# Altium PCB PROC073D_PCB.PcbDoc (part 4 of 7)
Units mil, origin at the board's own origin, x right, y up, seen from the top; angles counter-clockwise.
Board outline 2165.35 x 2695.12 mil, 8 copper layers (Top Layer, L2_GND, L3_SIGNAL 1, L4_SIGNAL 2, L5_SIGNAL 3, L6_SIGNAL 4, L7_GND, Bottom Layer), stack 56.1 mil thick; 414 components, 319 nets, 1353 pads, 1669 vias.
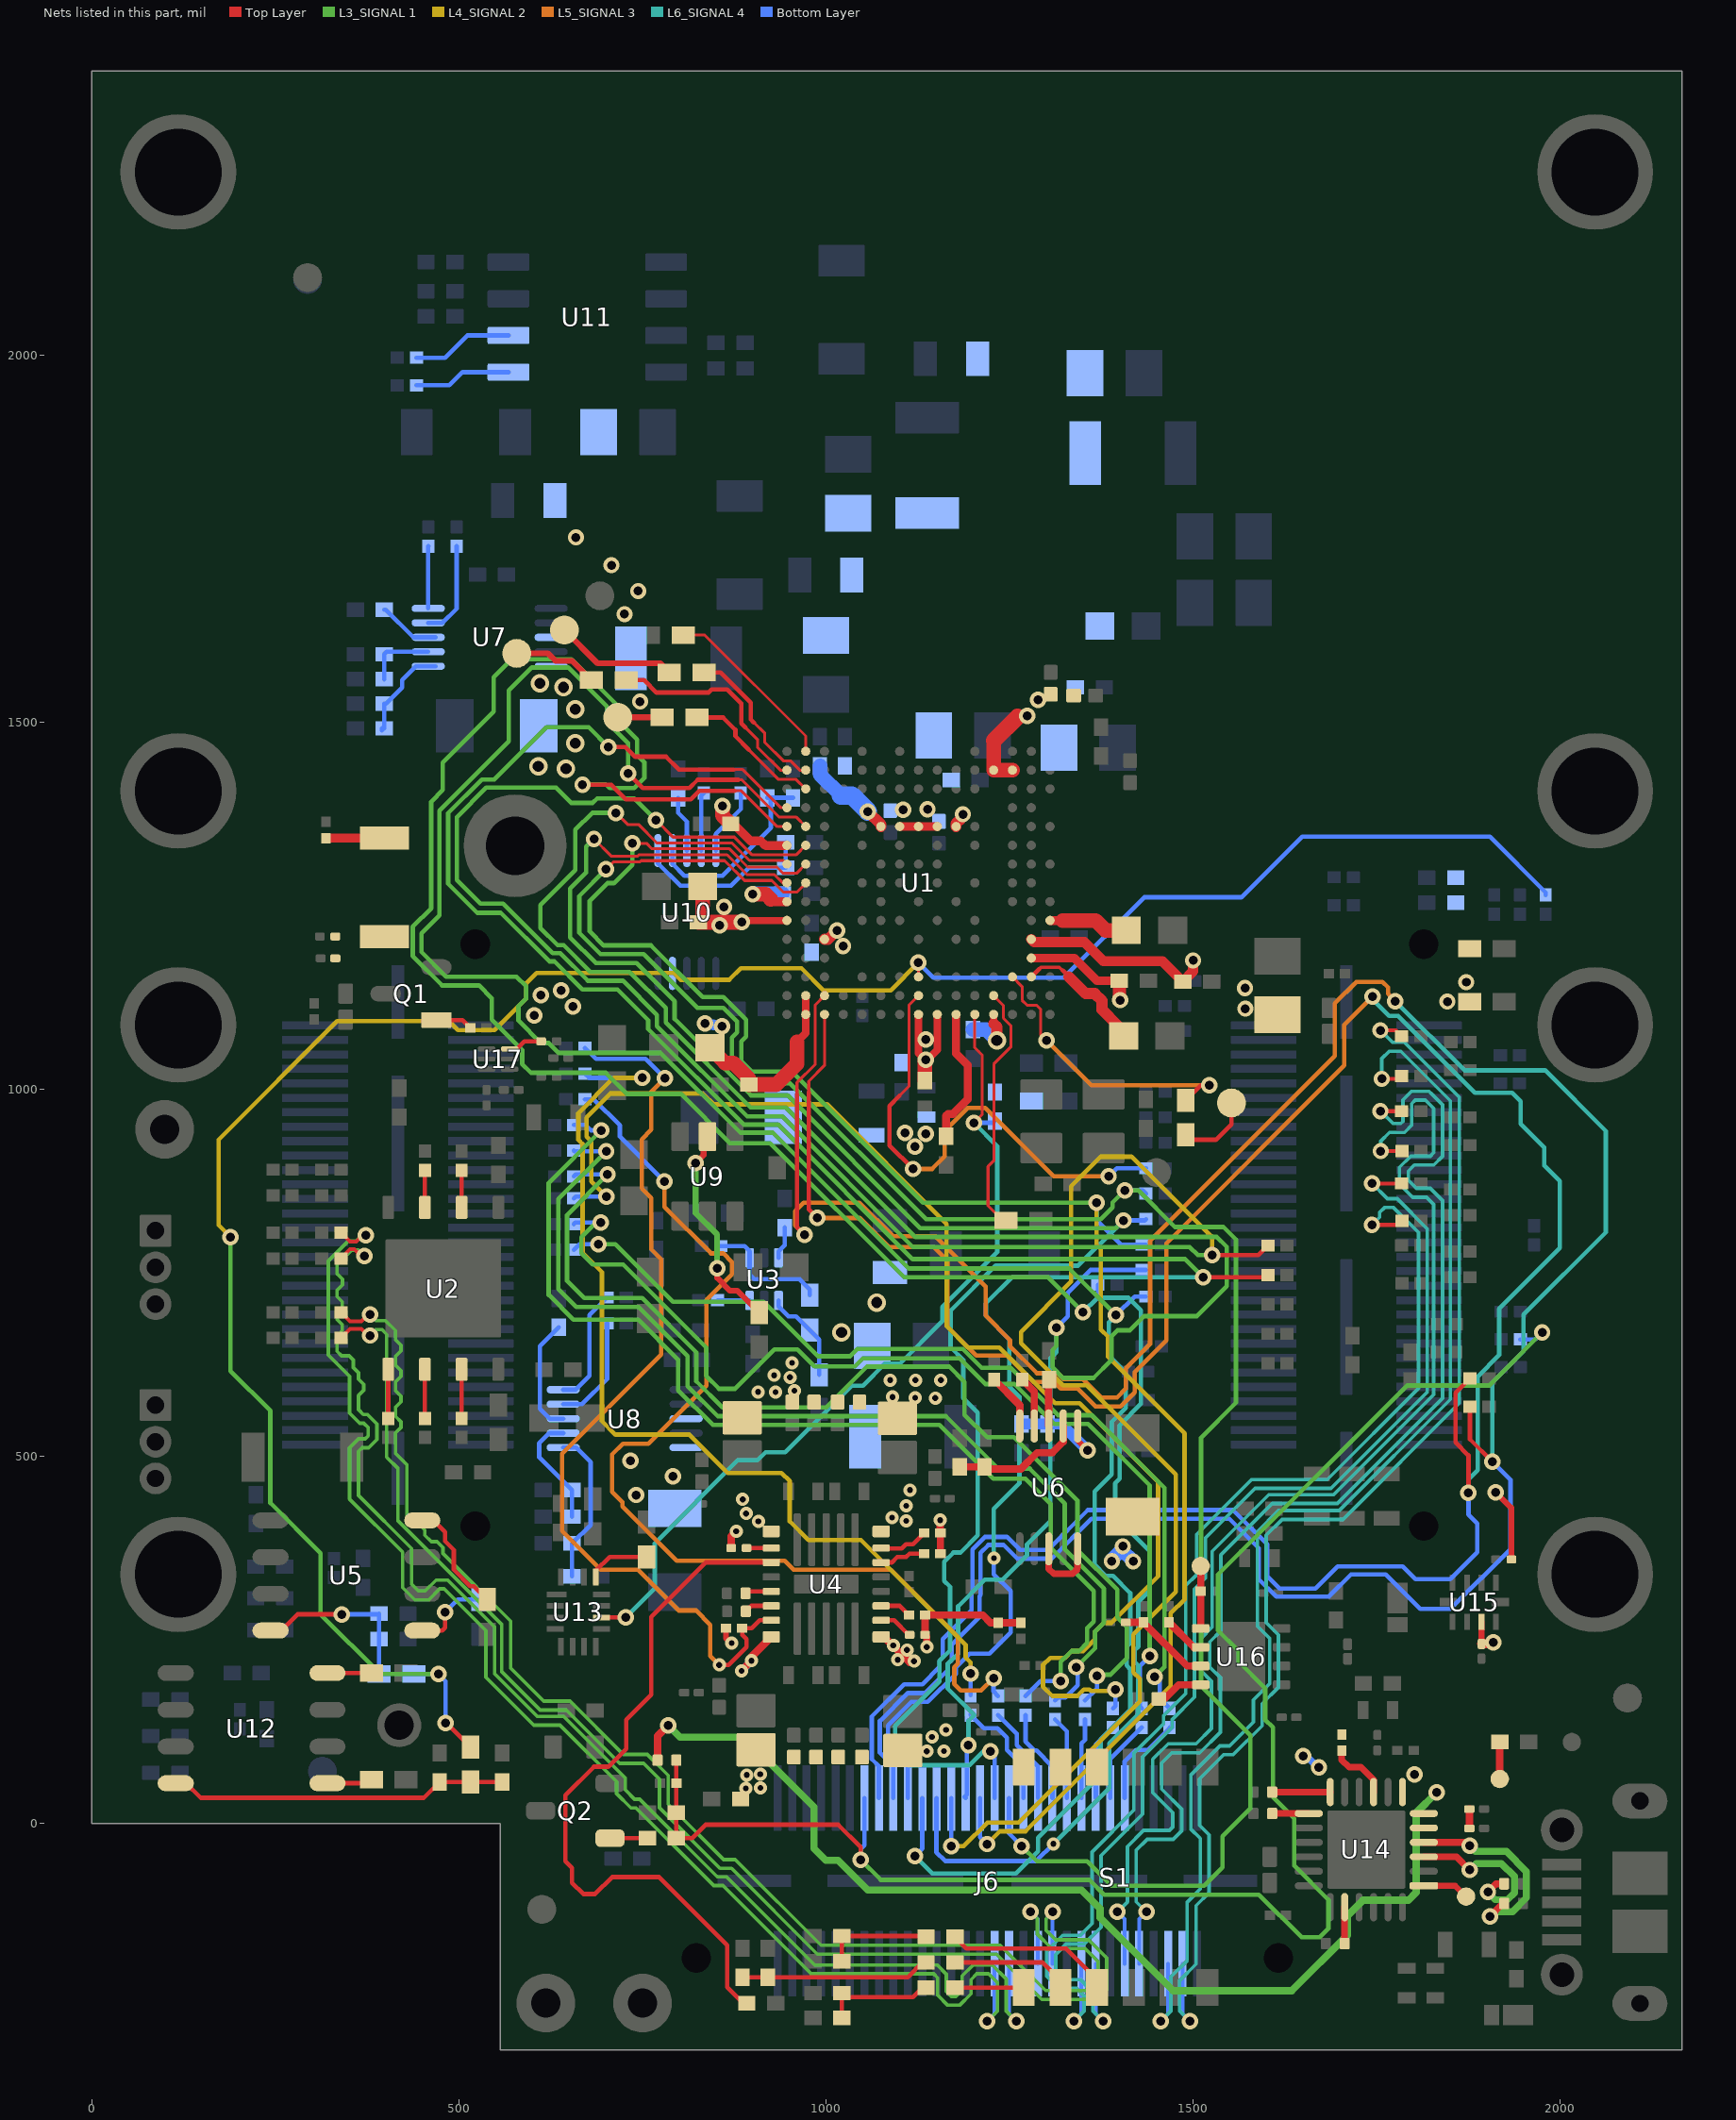
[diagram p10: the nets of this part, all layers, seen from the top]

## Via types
v1: diameter 13.77/15.74 (per signal layer), hole 5.9, Top Layer to L2_GND, tented both sides, 900 vias
v2: diameter 22.4, hole 12.2, Top Layer to Bottom Layer, tented both sides, 509 vias
v3: diameter 13.78/15.75 (per signal layer), hole 5.9, Top Layer to L2_GND, tented both sides, 72 vias
v4: diameter 18, hole 8, Top Layer to Bottom Layer, tented both sides, 71 vias
v5: diameter 22, hole 12.2, Top Layer to Bottom Layer, tented both sides, 57 vias
v6: diameter 25, hole 15, Top Layer to Bottom Layer, tented both sides, 28 vias
v7: diameter 19.68, hole 7.87, Top Layer to Bottom Layer, 16 vias
v8: diameter 13.77/15.74 (per signal layer), hole 5.9, Top Layer to L2_GND, tented top, 15 vias
v9: diameter 13.78/15.75 (per signal layer), hole 5.9, Top Layer to L2_GND, tented top, 1 vias

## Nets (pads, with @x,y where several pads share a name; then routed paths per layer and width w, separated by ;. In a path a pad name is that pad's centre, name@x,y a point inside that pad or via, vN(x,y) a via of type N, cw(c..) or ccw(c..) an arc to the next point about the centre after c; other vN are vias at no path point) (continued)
NetJ6_32: J6.32 R221.1 | length 1917
  Top Layer w5.2: R221.1@339.59,804.68 351.99,792.28 360.08,792.28 369.08,801.28 v2(373.31,801.28)
  L3_SIGNAL 1 w4.8: v2(373.31,801.28) 368.47,801.28 360.27,793.08 349.22,793.08 322.31,766.17 322.31,638.18 351.38,609.11 351.38,558.96 365.12,545.22 370.75,545.22 376.54,539.42 376.54,528.09 372.41,523.96 363.45,523.96 351.38,511.88 351.38,442.01 423.65,369.73 423.65,321.34 440.16,304.83 459.16,304.83 474.09,319.77 479.97,319.77 536.86,262.87 536.86,199.34 602.12,134.08 637.96,134.08 714.72,57.32 714.72,41.14 734.4,21.46 741.24,21.46 847.05,-84.35 859.64,-84.35 979.75,-204.45 1146.55,-204.45 1151.93,-209.83 1151.93,-233.42 1165.71,-247.2 1181.92,-247.2 1197.5,-231.63 1197.5,-212.32 1205.36,-204.45 1221.43,-204.45 1233.42,-216.45 1233.42,-255.17 v2(1219.69,-268.91)
  Bottom Layer w5.2: v2(1219.69,-268.91) 1229.58,-259.02 J6.32@1229.58,-190.65
NetJ6_34: J6.34 R222.1 | length 1923.5
  Top Layer w5.2: R222.1@339.59,769.68 351.99,782.08 357.63,782.08 366.83,772.88 v2(371.54,772.88)
  L3_SIGNAL 1 w4.8: v2(371.54,772.88) 363.34,781.08 354.19,781.08 334.31,761.2 334.31,748.81 341.65,741.47 341.65,733.76 334.31,726.42 334.31,717.71 341.47,710.55 341.47,702.47 334.31,695.31 334.31,686.6 341.47,679.44 341.47,671.37 334.31,664.2 334.31,643.16 340.47,637 350.6,637 356.3,631.29 356.3,621.16 363.38,614.09 363.38,605.38 370.54,598.21 370.54,590.14 363.38,582.98 363.38,563.93 370.09,557.22 375.72,557.22 388.54,544.39 388.54,523.12 377.38,511.96 368.42,511.96 363.38,506.91 363.38,446.98 435.65,374.7 435.65,326.31 445.13,316.83 454.18,316.83 469.12,331.77 484.94,331.77 548.86,267.84 548.86,204.31 607.09,146.08 642.93,146.08 726.72,62.29 726.72,46.11 739.37,33.46 746.21,33.46 852.02,-72.35 864.61,-72.35 984.72,-192.45 1151.52,-192.45 1163.93,-204.86 1163.93,-228.45 1170.68,-235.2 1176.95,-235.2 1185.5,-226.66 1185.5,-207.35 1200.39,-192.45 1226.4,-192.45 1245.42,-211.48 1245.42,-255.17 v2(1259.16,-268.91)
  Bottom Layer w5.2: J6.34@1249.27,-190.65 1249.27,-259.02 v2(1259.16,-268.91)
NetJ6_35: J6.35 R148.2 | length 155
  Bottom Layer w6: R148.2@1196.94,149.12 R148.2@1196.94,147.88 1215,129.82 1233.76,129.82 1246.45,117.12 1246.45,100.65 1268.95,78.16 J6.35@1268.95,34.94
NetJ6_37: J6.37 R149.2 | length 135.6
  Bottom Layer w6: R149.2@1234.31,147.88 1259.67,122.51 1259.67,106.83 1277.89,88.62 1278.17,88.62 1288.64,78.16 J6.37@1288.64,34.94
NetJ6_38: J6.38 R223.1 | length 1896.9
  Top Layer w5.2: R223.1@339.59,696.43 351.99,684.03 367.5,684.03 376.59,693.12 v2(379.02,693.12)
  L3_SIGNAL 1 w4.8: v2(379.02,693.12) 387.22,684.92 400.27,684.92 413.84,671.36 413.84,658.98 421.18,651.63 421.18,643.92 413.84,636.58 413.84,624.2 421.18,616.85 421.18,609.14 413.84,601.8 413.84,589.42 421.18,582.07 421.18,574.36 413.84,567.02 413.84,554.64 421.18,547.29 421.18,539.58 413.84,532.24 413.84,504.14 429.28,488.7 429.28,417.24 438.03,408.49 445.21,408.49 453.87,399.83 453.87,392.65 462.62,383.89 470.54,383.89 478.46,375.97 478.46,368.06 570.59,275.93 570.59,211.85 615.66,166.78 651.51,166.78 724.02,94.26 756.63,94.26 785.26,65.64 785.26,26.66 860.68,-48.77 876.4,-48.77 993.2,-165.57 1237.24,-165.57 1298.95,-227.27 1364.28,-227.27 1370.32,-221.23 1370.32,-187.72 1352.67,-170.07 1307.45,-170.07 1287.86,-150.47 1287.86,-129.57 1278.74,-120.46 v2(1278.74,-120.14)
  Bottom Layer w5.2: v2(1278.74,-120.14) 1288.64,-130.04 J6.38@1288.64,-190.65
NetJ6_39: J6.39 R163.2 | length 129.8
  Bottom Layer w6: R163.2@1271.67,147.88 1271.67,111.95 1283.88,99.74 1286.73,99.74 1308.32,78.16 J6.39@1308.32,34.94
NetJ6_40: J6.40 R224.1 | length 1880.3
  Top Layer w5.2: R224.1@339.59,661.43 351.99,673.83 367.48,673.83 376.59,664.72 v2(379.02,664.72)
  L3_SIGNAL 1 w4.8: v2(379.02,664.72) 387.22,672.92 395.3,672.92 401.84,666.39 401.84,499.17 417.28,483.73 417.28,412.27 558.59,270.95 558.59,206.88 610.69,154.78 646.54,154.78 719.05,82.26 751.66,82.26 773.26,60.67 773.26,21.69 855.71,-60.77 871.43,-60.77 988.23,-177.57 1232.27,-177.57 1293.98,-239.27 1369.25,-239.27 1382.32,-226.2 1382.32,-182.75 1357.64,-158.07 1312.42,-158.07 1299.86,-145.5 1299.86,-129.57 1308.97,-120.46 v2(1308.97,-120.14)
  Bottom Layer w5.2: J6.40@1308.32,-190.65 1308.32,-120.19 v2@1308.97,-119.54
NetJ6_41: J6.41 R164.2 | length 113.6
  Bottom Layer w6: R164.2@1311.95,141.89 1328.01,125.83 J6.41@1328.01,34.94
NetJ6_43: J6.43 R166.2 | length 109
  Bottom Layer w6: J6.43@1347.69,34.94 1347.69,109.19 1352.68,114.18 R166.2@1352.68,141.89
NetJ6_44: J6.44 R225.1 | length 1615.3
  Top Layer w5.2: v5(1743.35,815.38) 1778.97,815.38 R225.1@1784.28,820.68
  L6_SIGNAL 4 w4.8: v2(1337.8,-268.91) 1351.53,-255.17 1351.53,-234.62 1341.14,-224.23 1317.58,-224.23 1300.76,-207.41 1300.76,-173.37 1322.17,-151.96 1346.44,-151.96 1362.42,-135.98 1362.42,-38.46 1419.03,18.15 1419.03,95.77 1459.53,136.27 1459.53,146.95 1489.86,177.28 1489.86,324.27 1504.76,339.17 1504.76,394.03 1579.36,468.63 1682.66,468.63 1806.78,592.74 1806.78,805.02 1772.82,838.97 1760.45,838.97 1753.74,832.27 1753.74,825.77 v5(1743.35,815.38)
  Bottom Layer w5.2: v2(1337.8,-268.91) 1347.69,-259.02 J6.44@1347.69,-190.65
NetJ6_45: J6.45 R167.2 | length 105.8
  Bottom Layer w6: J6.45@1367.38,34.94 1367.38,107.64 R167.2@1390.77,131.04
NetJ6_46: J6.46 R226.1 | length 1627.1
  Top Layer w5.2: v5(1743.62,871.84) R226.1@1783.86,871.84
  L6_SIGNAL 4 w4.8: v2(1377.27,-268.91) 1363.53,-255.17 1363.53,-229.65 1346.11,-212.23 1322.55,-212.23 1312.76,-202.44 1312.76,-178.34 1327.14,-163.96 1351.41,-163.96 1374.42,-140.95 1374.42,-43.43 1431.03,13.18 1431.03,90.8 1471.53,131.3 1471.53,141.98 1501.86,172.31 1501.86,319.3 1516.76,334.2 1516.76,389.06 1584.33,456.63 1687.63,456.63 1818.78,587.77 1818.78,809.99 1777.79,850.97 1764.49,850.97 v5(1743.62,871.84)
  Bottom Layer w5.2: J6.46@1367.38,-190.65 1367.38,-259.02 v2(1377.27,-268.91)
NetJ6_47: J6.47 R168.2 | length 113.9
  Bottom Layer w6: J6.47@1387.06,34.94 1387.06,88.18 R168.2@1429.92,131.04
NetJ6_49: J6.49 R170.2 | length 130.8
  Bottom Layer w6: J6.49@1406.75,34.94 1406.75,84.76 1422.61,100.63 1438.62,100.63 1467.83,129.84 R170.2@1467.83,131.04
NetJ6_50: J6.50 R227.1 | length 1701.5
  Top Layer w5.2: v5(1755.37,915.68) 1783.92,915.68 R227.1@1784.28,916.04
  L6_SIGNAL 4 w4.8: v2(1396.85,-120.14) 1410.46,-106.53 1410.46,-31.11 1432.38,-9.2 1467.76,-9.2 1472.29,-4.66 1472.29,14.93 1445.01,42.22 1445.01,87.75 1465.94,108.69 1504,108.69 1524.97,129.65 1524.97,193.98 1510.56,208.39 1510.56,252.5 1525.82,267.77 1525.82,370.85 1602.9,447.93 1691.24,447.93 1827.48,584.17 1827.48,843.37 1817.82,853.03 1798.93,853.03 1780.94,871.02 1780.94,893.62 1796.25,908.93 1822.75,908.93 1827.48,913.65 1827.48,973.99 1816.28,985.18 1802.19,985.18 1797.58,980.57 1797.58,951.13 1787.83,941.38 1767.2,941.38 1755.37,929.55 v5(1755.37,915.68)
  Bottom Layer w5.2: v2(1396.85,-120.14) 1406.75,-130.04 J6.50@1406.75,-190.65
NetJ6_52: J6.52 R228.1 | length 1715
  Top Layer w5.2: v5(1754.92,970.18) R228.1@1783.86,970.18
  L6_SIGNAL 4 w4.8: v2(1436.33,-120.14) 1422.46,-106.27 1422.46,-36.08 1437.35,-21.2 1472.73,-21.2 1484.29,-9.63 1484.29,19.9 1457.01,47.19 1457.01,82.78 1470.91,96.69 1508.97,96.69 1536.97,124.68 1536.97,198.95 1522.56,213.36 1522.56,247.53 1537.82,262.8 1537.82,365.88 1607.87,435.93 1696.21,435.93 1839.48,579.2 1839.48,848.34 1822.79,865.03 1803.9,865.03 1792.94,875.99 1792.94,888.65 1801.22,896.93 1827.72,896.93 1839.48,908.68 1839.48,978.96 1824.23,994.2 1821.25,997.18 1797.22,997.18 1785.58,985.54 1785.58,956.1 1782.86,953.38 1772.17,953.38 1755.6,969.95 v5@1755.82,970.18 ; v5(1754.92,970.18) v5@1755.82,970.18 ; v5@1759.03,973.39 v5@1755.82,970.18
  Bottom Layer w5.2: J6.52@1426.43,-190.65 1426.43,-130.04 v2(1436.33,-120.14)
NetJ6_56: J6.56 R229.1 | length 1761.2
  Top Layer w5.2: v5(1756.84,1014.18) 1780.15,1014.18 R229.1@1783.86,1017.88
  L6_SIGNAL 4 w4.8: v2(1455.91,-268.91) 1469.64,-255.17 1469.64,-208.48 1491.93,-186.2 1491.93,-106.58 1509.62,-88.88 1509.62,-20.15 1496.76,-7.29 1496.76,66.18 1536.49,105.91 1549.58,105.91 1581.94,138.26 1581.94,168.41 1604.1,190.57 1604.1,252.31 1587.46,268.94 1587.46,397.7 1616.14,426.38 1698.96,426.38 1850.28,577.69 1850.28,984.22 1782.66,1051.84 1766.99,1051.84 1756.84,1041.69 v5(1756.84,1014.18)
  Bottom Layer w5.2: v2(1455.91,-268.91) 1465.8,-259.02 J6.56@1465.8,-190.65
NetJ6_58: J6.58 R230.1 | length 1761.5
  Top Layer w5.2: v5(1755,1080.24) 1775.98,1080.24 R230.1@1783.86,1072.37
  L6_SIGNAL 4 w4.8: v2(1495.38,-268.91) 1481.64,-255.17 1481.64,-213.45 1503.93,-191.17 1503.93,-111.55 1521.62,-93.85 1521.62,-15.18 1508.76,-2.32 1508.76,61.21 1541.46,93.91 1554.55,93.91 1593.94,133.29 1593.94,163.44 1616.1,185.6 1616.1,257.28 1599.46,273.91 1599.46,392.73 1621.11,414.38 1703.93,414.38 1862.28,572.72 1862.28,989.19 1787.63,1063.84 1771.39,1063.84 v5(1755,1080.24)
  Bottom Layer w5.2: J6.58@1485.49,-190.65 1485.49,-259.02 v2(1495.38,-268.91)
NetQ1_1: Q1.1 R171.2 | length 50.6
  Top Layer w6: Q1.1@469.47,1094.24 505.1,1094.24 R171.2@515.68,1083.65
NetQ2_1: Q2.1 R179.2 | length 51.6
  Top Layer w6: Q2.1@705.91,-19.74 R179.2@757.47,-19.74
NetR2_1: R2.1 R101.2 U6.2 | length 179.2
  Top Layer w10: R101.2@1182.13,485.85 R2.1@1215.81,485.88 1218.77,482.92 1265.4,482.92 1287.55,505.07 1308.25,505.07 1323.04,519.86 U6.2@1323.04,541.59
NetR3_1: R3.1 R70.2 R71.1 U5.8 | length 239.4
  Top Layer w6: U5.8@243.74,263.05 258.63,263.05 280.6,285.03 v2(340.45,285.03)
  Bottom Layer w6: v2(340.45,285.03) 390.67,285.03 R71.1@391.55,285.9 R70.2@391.55,251.6 R3.1@391.55,203.79
NetR14_1: R14.1 R103.2 U6.1 | length 143.9
  Top Layer w8: U6.1@1342.73,541.59 1342.73,521.98 v2(1356.41,508.3)
  Bottom Layer w15: R103.2@1266.47,544.49 1320.22,544.49 v2(1356.41,508.3)
NetR25_1: R25.1 U6.5 | length 77.6
  Top Layer w10: R25.1@1229.01,604.74 1263.99,569.76 U6.5@1263.99,541.59
NetR29_1: R29.1 U6.4 | length 70
  Top Layer w10: R29.1@1267.18,604.74 1283.67,588.24 U6.4@1283.67,541.59
NetR45_1: R45.1 U2.5 | length 66.8
  Top Layer w6: R45.1@403.88,551.84 U2.5@403.88,618.61
NetR46_2: R46.2 U2.2 | length 50.7
  Top Layer w6: U2.2@503.88,839.09 R46.2@503.88,889.77
NetR47_2: R47.2 U2.3 | length 50.7
  Top Layer w6: U2.3@453.88,839.09 R47.2@453.88,889.77
NetR48_1: R48.1 U2.6 | length 66.8
  Top Layer w6: R48.1@453.88,551.84 U2.6@453.88,618.61
NetR51_1: R51.1 U2.7 | length 66.8
  Top Layer w6: R51.1@503.88,551.84 U2.7@503.88,618.61
NetR54_1: R54.1 U3.3 | length 44.6
  Bottom Layer w6: U3.3@935.43,770.56 935.43,779.17 943.74,787.49 R54.1@943.74,811.74
NetR55_2: R55.2 U3.6 | length 43.8
  Bottom Layer w6: R55.2@852.47,712.79 852.97,712.29 U3.6@896.06,712.3
NetR56_2: R56.2 R151.1 U3.1 | length 172.4
  Bottom Layer w6: R56.2@856.74,786.43 889.16,786.43 896.06,779.53 896.06,747.37 902,741.43 964,741.43 977.93,727.5 R151.1@977.93,719.5
NetR57_1: R57.1 R151.2 U3.4 | length 130.1
  Bottom Layer w6: U3.4@935.43,712.3 935.43,704.19 948.74,690.88 959.31,690.88 R151.2@977.93,672.26 990.93,659.26 R57.1@990.93,611.38
NetR72_2: R72.2 U1.P1 | length 244.8
  Top Layer w4.02: R72.2@805.74,1618.43 835.06,1618.43 972.43,1481.06 U1.P1@972.44,1460.18 U1.P1@972.64,1459.97
NetR73_2: R73.2 U1.P2 | length 214.8
  Top Layer w4: 901.74,1499.61 916.74,1484.61 916.74,1472.23 941.73,1447.24 951.59,1447.24 959.14,1439.68 959.14,1439.51 964.27,1434.38 U1.P2@972.64,1434.38
  Top Layer w6: R73.2@833.93,1567.75 856.56,1567.75 897.74,1526.57 897.74,1503.61 901.74,1499.61
NetR74_2: R74.2 U1.P3 | length 193.7
  Top Layer w4: 895.24,1462.13 935.43,1421.95 959.48,1421.95 U1.P3@972.44,1409
  Top Layer w6: R74.2@824.21,1506.43 824.41,1506.23 859.94,1506.23 876.74,1489.43 876.74,1480.63 895.24,1462.13
NetR75_2: R75.2 U1.R2 | length 295.9
  Top Layer w4.02: 890.74,1492.4 906.73,1476.41 906.73,1465.77 938.12,1434.38 U1.R2@947.05,1434.38
  Top Layer w6: R75.2@727.75,1557.21 752.3,1557.21 769.3,1540.2 840.02,1540.2 844.44,1544.63 865.54,1544.63 884.74,1525.43 884.74,1498.4 890.74,1492.4
NetR76_2: R76.2 U1.C13 | length 400.4
  Top Layer w4: U1.C13@1254.13,1152.88 1267.08,1139.94 1267.08,1121.29 1274.08,1114.29 1287.08,1114.29 1292.08,1109.29 1292.08,1074.94 v2(1300.59,1066.43)
  Top Layer w6: R76.2@1490,985.05 1510.38,1005.43 v2(1522,1005.43)
  L5_SIGNAL 3 w6: v2(1300.59,1066.43) 1361.59,1005.43 v2(1522,1005.43)
NetR77_2: R77.2 U1.D14 | length 340.9
  Top Layer w4: U1.D14@1228.54,1127.29 1241.63,1114.2 1241.63,1096.82 1251.63,1086.81 1251.63,1057.41 1228.53,1034.31 1228.53,902.72 1220.74,894.93 1220.74,841.43 1240.74,821.43 R77.2@1245.12,821.43
NetR78_2: R78.2 U5.1 | length 108.1
  Top Layer w6: U5.1@450.43,263.05 477.66,263.05 481.44,266.84 v2(481.44,287.75)
  Bottom Layer w6: v2(481.44,287.75) 498.88,305.18 R78.2@528.88,305.18
NetR80_2: R80.2 U5.4 | length 156.2
  Top Layer w6: U5.4@450.43,413.05 465.37,413.05 481.19,397.23 481.19,384.71 493.28,372.62 493.28,345.78 515.67,323.39 520.67,323.39 R80.2@538.88,305.18
NetR83_2: R83.2 R84.1 R216.1 U12.8 | length 461.7
  Top Layer w6: U12.8@114.6,55.08 128.68,55.08 148.51,35.25 452.36,35.25 R84.1@474.08,56.97 R216.1@516.22,56.97 R83.2@559.05,56.97
NetR85_2: R85.2 U12.1 | length 61.7
  Top Layer w6: U12.1@321.29,55.08 375.94,55.08 R85.2@380.94,60.08
NetR87_2: R87.2 U12.4 | length 59.7
  Top Layer w6: U12.4@321.29,205.08 R87.2@380.94,205.08
NetR89_2: R89.2 U13.13 | length 85.3
  Top Layer w6: U13.13@686.41,335.85 686.41,344.3 705.38,363.27 R89.2@755.42,363.27
NetR91_1: R91.1 U14.3 | length 235.5
  Top Layer w9.42: U14.3@1814.14,-45.14 1858.43,-45.14 v2(1876.29,-63) ; v2(1901.27,-92.68) 1912.13,-81.82 R91.1@1923.38,-81.82
  L3_SIGNAL 1 w9.42: v2(1876.29,-63) 1885.14,-54.16 1919.66,-54.16 1937.37,-71.87 1937.37,-94.21 1928.08,-103.5 1911.27,-103.5 1901.27,-93.5 v2(1901.27,-92.68)
NetR92_1: R92.1 U14.4 | length 278.8
  Top Layer w9.42: U14.4@1814.14,-25.46 1871.86,-25.46 v2(1876.29,-29.89) ; v2(1904.03,-126.16) 1921.72,-108.48 R92.1@1923.38,-108.48
  L3_SIGNAL 1 w9.42: v2(1876.29,-29.89) 1884.14,-37.74 1926.46,-37.74 1953.79,-65.07 1953.79,-101.01 1934.88,-119.92 1910.28,-119.92 v2(1904.03,-126.16)
NetR93_2: R93.2 U14.9 | length 83.6
  Top Layer w9: R93.2@1702.37,99.32 1702.37,86.62 1712.17,76.82 1728.25,76.82 1745.65,59.42 U14.9@1745.65,43.03
NetR94_2: R94.2 U6.3 | length 63.4
  Top Layer w10: U6.3@1303.36,541.59 1303.36,604.23 R94.2@1303.87,604.74
NetR96_1: R96.1 U14.20 | length 49.5
  Top Layer w9: R96.1@1706.28,-163.08 U14.20@1706.28,-113.63
NetR97_1: R97.1 U14.12 | length 79
  Top Layer w9: R97.1@1607.62,43.03 U14.12@1686.6,43.03
NetR98_2: R98.2 U14.13 | length 49.9
  Top Layer w9: R98.2@1607.62,13.91 U14.13@1657.48,13.91
NetR102_2: R102.2 R120.2 U16.3 | length 126.7
  Top Layer w10: R102.2@1408.25,274.12 R120.2@1432.23,274.14 ; R120.2@1432.23,274.14 1491.63,214.74 U16.3@1510.32,214.74
NetR104_1: R104.1 R113.2 U7.2 | length 94.7
  Bottom Layer w6: R104.1@398.53,1558.28 R104.1@398.53,1558.68 R113.2@398.53,1591.71 ; R113.2@398.53,1592.31 401.93,1595.72 U7.2@458.41,1595.72
NetR105_1: R105.1 R114.2 U7.1 | length 133.5
  Bottom Layer w6: R114.2@395.38,1488.43 R114.2@395.38,1491.43 ; R114.2@398.53,1491.43 R105.1@398.53,1524.86 ; R105.1@398.53,1525.06 401.1,1525.06 422.88,1546.84 422.88,1557.29 441.62,1576.03 U7.1@458.41,1576.03 U7.1@468.41,1576.03
NetR106_1: R106.1 R116.2 U8.2 | length 157.1
  Bottom Layer w6: U8.2@642.2,531.87 623.21,531.87 609.47,518.14 609.47,499.08 R116.2@654.32,454.23 R106.1@654.32,418.02
NetR107_1: R107.1 R117.2 U8.1 | length 211.5
  Bottom Layer w6: U8.1@642.2,512.19 659.67,512.19 679.64,492.22 679.64,407.12 R117.2@654.32,381.8 R107.1@654.32,336.97
NetR108_1: R108.1 U7.5 | length 84.8
  Bottom Layer w6: U7.5@458.41,1654.77 458.41,1739.36 R108.1@458.56,1739.51
NetR109_1: R109.1 U8.5 | length 160.4
  Bottom Layer w6: U8.5@642.2,590.93 659.4,590.93 678.11,609.64 678.11,692.53 R109.1@702.01,716.43
NetR110_1: R110.1 U7.4 | length 131.8
  Bottom Layer w6: U7.4@458.41,1635.09 477.67,1635.08 497.17,1654.58 R110.1@497.17,1739.51
NetR111_1: R111.1 U8.4 | length 149.9
  Bottom Layer w6: U8.4@642.2,571.24 667.74,571.24 702.01,605.51 R111.1@702.01,681.43
NetR112_2: R112.2 U7.3 | length 85.5
  Bottom Layer w6: R112.2@398.53,1653.12 400.43,1653.12 438.16,1615.4 U7.3@458.41,1615.4 U7.3@468.41,1615.4
NetR115_2: R115.2 U8.3 | length 159.1
  Bottom Layer w6: R115.2@636.16,676.01 610.41,650.26 610.41,564.95 623.8,551.56 U8.3@642.2,551.56
NetR118_2: R118.2 TP8.1 U16.1 | length 84.9
  Top Layer w10: U16.1@1510.32,265.92 R118.2@1510.32,316.41 TP8.1@1510.32,350.86
NetR119_1: R119.1 U16.2 | length 57.3
  Top Layer w10: R119.1@1467.08,274.14 1500.89,240.33 U16.2@1510.32,240.33
NetR121_2: R121.2 U16.4 | length 65
  Top Layer w10: R121.2@1453.31,169.94 1460.9,169.94 1480.1,189.15 U16.4@1510.32,189.15
NetR138_2: R138.2 U17.3 | length 47.2
  Top Layer w6: U17.3@569.32,1054.92 578.93,1054.92 589.3,1065.29 R138.2@612.21,1065.29
NetR139_1: R139.1 R146.2 U10.2 | length 261.4
  Bottom Layer w6: U10.2@790.91,1325.09 790.91,1307.11 807.29,1290.72 859.29,1290.72 925,1356.43 R146.2@925,1396.74 ; R146.2@920.18,1396.92 R139.1@955.18,1396.92
NetR142_1: R142.1 R147.2 U10.1 | length 249.1
  Bottom Layer w6: U10.1@771.22,1325.09 771.22,1307.72 801.67,1277.27 870.84,1277.27 895,1301.43 R147.2@945.32,1301.43 R142.1@945.32,1336.43
NetR143_1: R143.1 U10.5 | length 92.6
  Bottom Layer w6: U10.5@849.96,1325.09 849.96,1347.64 883.92,1381.61 R143.1@883.92,1403.61
NetR144_1: R144.1 U10.4 | length 79.8
  Bottom Layer w6: U10.4@830.28,1325.09 830.28,1399.97 R144.1@833.74,1403.44
NetR145_2: R145.2 U10.3 | length 76.6
  Bottom Layer w6: R145.2@798.74,1396.74 798.74,1376.43 810.59,1364.58 U10.3@810.59,1325.09
NetR159_1: R159.1 U11.6 | length 137.9
  Bottom Layer w6: R159.1@442.4,1996.15 481.23,1996.15 511.51,2026.43 U11.6@567.72,2026.43
NetR160_1: R160.1 U11.5 | length 132.7
  Bottom Layer w6: R160.1@442.4,1958.61 487.23,1958.61 505.05,1976.43 U11.5@567.72,1976.43
NetR196_2: R196.2 U9.5 | length 288
  Top Layer w8: v2(822.43,899.52) 833.46,910.54 833.46,930.28 U9.5@838.74,935.56 ; v2(851.75,756.4) 851.75,743.18 869.27,725.66 879.35,725.66 R196.2@908.98,696.03
  L3_SIGNAL 1 w8: v2(822.43,899.52) 822.43,831.5 851.75,802.18 v2(851.75,756.4)
NetR203_2: R203.2 R204.1 R205.2 | length 155.7
  Top Layer w6: R205.2@1021.73,-264.45 R203.2@1021.73,-230.73 1026.93,-235.93 1118.35,-235.93 1131.08,-223.19 R204.1@1136.29,-223.19
NetR204_2: R204.2 S1.1 | length 93.5
  Top Layer w6: R204.2@1175.66,-223.19 S1.1@1269.21,-223.19
NetR206_2: R206.2 R207.1 R208.2 | length 258.4
  Top Layer w6: R208.2@886.26,-209.04 R206.2@920.56,-209.04 1111.3,-209.04 1131.47,-188.88 R207.1@1136.29,-188.88
NetR207_2: R207.2 S1.2 | length 163.3
  Top Layer w6: R207.2@1175.66,-188.88 1294.32,-188.88 1319.21,-213.76 S1.2@1319.21,-223.19
NetR209_2: R209.2 R210.1 R211.2 | length 148.5
  Top Layer w6: R211.2@1021.73,-187.4 R209.2@1021.73,-153.92 ; R209.2@1021.73,-152.92 1135.29,-152.92 R210.1@1136.29,-153.92
NetR210_2: R210.2 S1.3 | length 228.4
  Top Layer w6: R210.2@1175.66,-154.56 1191.03,-169.94 1326.9,-169.94 1369.21,-212.24 S1.3@1369.21,-223.19
NetR213_1: R213.1 S3.2 | length 79.3
  Top Layer w12: R213.1@319.32,1341.9 S3.2@398.63,1341.9
NetR214_1: R214.1 R215.2 S3.1
NetTP1_1: TP1.1 U14.1 | length 63.5
  Top Layer w8: U14.1@1814.14,-84.51 1856.81,-84.51 TP1.1@1871.57,-99.27
PGOOD: J6.13 R13.2 R179.1 R182.2 R198.1 R201.2 | length 2322.5
  Top Layer w6: R198.1@796.29,86.51 R182.2@796.29,14.84 R179.1@796.29,-19.74 817.72,-19.74 836.04,-1.42 1016.78,-1.42 1047.36,-32 v2(1047.36,-49.24)
  L3_SIGNAL 1 w6: v2(1047.36,-49.24) 1074.58,-76.46 1358.51,-76.46 1378.73,-96.68 1589.54,-96.68 1647.57,-154.71 1672.49,-154.71 1684.07,-143.13 1684.07,-103.51 1637.71,-57.15 1637.71,7.29 1608.52,36.48 1608.52,131.03 1598,141.55 1598,184.54 1561.64,220.89 1561.64,235.34 1533.81,263.17 1533.81,339.53 1790.89,596.61 1903.04,596.61 v2(1975.14,668.71)
  Bottom Layer w6: v2(1047.36,-49.24) 1047.36,-34.21 1052.42,-29.15 J6.13@1052.42,34.94 ; R13.2@1945.35,659.47 1965.91,659.47 v2(1975.14,668.71)
PMIC_1V0: C66.1 C98.1 L6.1 R199.1 U4.1 U7.8 U7.10
  other v2: 603,1100.34 655.35,1112.72 611.93,1128.11 639.4,1134.33
  other v4: 908.03,411.72 891.27,422.3 886.66,441.58 931.29,587.79 907.69,587.96 956.93,589.48 950.98,607.82 929.26,610.59 953.83,627.6
  other v6: 646.03,1436.35 608.27,1439.56 658.53,1471.39 658.53,1517.51 642.69,1547.41 610.68,1552.89
PMIC_1V2: C62.1 C91.1 L5.1 R193.1 U4.14 U8.8 U8.10 | length 59.7
  Top Layer w5.5: U4.14@1075.13,254.29 U4.14@1079.07,254.29
  Top Layer w10: U4.14@1079.07,254.29 1113.6,219.76 1115.1,221.26 v4(1119.91,221.26)
  other v2: 741.58,447.62 791.44,473.25 733.55,494.03
  other v4: 1137.26,98.63 1160.5,99.01 1144.41,117.95 1163.45,127.73 1097.83,223.25 1110.23,236.51 1091.61,242.63
PMIC_1V8: C67.1 C99.1 L8.1 R192.1 U4.21 U6.8 U6.10 | length 148.3
  Top Layer w9: U6.8@1303.36,374.27 1303.36,346.93 1310.07,340.22 1335.8,340.22 1342.73,347.15 U6.10@1342.73,374.27
  Bottom Layer w18.7: v5(1389.2,357.37) 1389.2,359.43 v5@1402.59,372.82 ; v5(1404.24,377.72) 1404.24,374.47 v5@1402.59,372.82 ; v5(1418.3,357.12) v5@1402.59,372.82
  other v4: 1109.31,412.39 1090.02,416.81 1109.09,432.93 1114.48,454.24 1148.84,579.61 1121.3,579.98 1090.56,580.94 1087.33,604 1121.86,604 1156.38,604
PMIC_3V3: C61.1 C90.1 L4.1 L12.2 U4.8 | length 82.3
  Top Layer w10: v4(885.17,208.11) 885.17,208.49 v4(898.61,221.94) 898.61,227.38 U4.8@925.53,254.29
  Bottom Layer w10: v4(885.17,208.11) 898.61,221.55 v4(898.61,221.94)
  other v4: 891.01,48 910.71,48.9 892.32,66.3 910.48,67.41
PMIC_CLK: R202.2 U4.3 | length 978.2
  Top Layer w6: R202.2@892.19,-244.3 887.13,-244.3 865.54,-222.7 865.54,-165.56 772.71,-72.73 708.71,-72.73 685.73,-95.72 669.5,-95.72 654.31,-80.52 654.31,-60.1 645.26,-51.05 645.26,38.79 684.03,77.56 703.51,77.56 727.84,101.89 727.84,141.6 761.87,175.62 761.87,281.59 835.94,355.67 U4.3@925.53,355.67
PMIC_EN1: R140.1 R188.1 U4.7 | length 1256.2
  Top Layer w6: v4(854.61,216.21) 867.43,216.21 891.65,240.43 891.65,251.25 885.96,256.94 R188.1@885.96,266.16 898.93,266.16 909.7,276.93 U4.7@925.53,276.93
  L5_SIGNAL 3 w6: v2(780.6,1015.11) 762.25,996.76 762.25,945.01 749.05,931.81 749.05,864.81 762.02,851.84 762.02,782.3 775.68,768.64 775.68,638.79 640.71,503.81 640.71,398.36 693.33,345.74 744.14,345.74 799.57,290.31 823.03,290.31 842.54,270.8 842.54,228.28 v4(854.61,216.21)
  Bottom Layer w6: R140.1@671.74,1056.43 686.71,1041.45 754.26,1041.45 v2(780.6,1015.11)
PMIC_EN2: R189.1 U4.15 | length 47
  Top Layer w6: U4.15@1075.13,276.93 1092.71,276.93 1112.48,257.16 R189.1@1113.9,257.16
PMIC_EN3: R190.1 U4.2 | length 33.6
  Top Layer w6: R190.1@891.97,375.35 U4.2@925.53,375.35
PMIC_NINT: R177.1 U4.19 | length 63.6
  Top Layer w6: U4.19@1075.13,355.67 1089.6,355.67 1097.02,363.09 1109.2,363.09 1113.78,367.66 R177.1@1133.78,367.66
PMIC_NRST: R187.1 U4.20 | length 67.8
  Top Layer w6: U4.20@1075.13,375.35 1075.82,374.66 1103.01,374.66 1109.02,380.67 1118.45,380.67 R187.1@1133.78,396.01
PMIC_PGOOD: R176.1 U4.16 | length 43
  Top Layer w6: U4.16@1075.13,296.61 1100.49,296.61 R176.1@1112.94,284.16
PMIC_SCL: R181.2 U4.5 | length 36
  Top Layer w6: R181.2@890.6,313.66 893.24,316.3 U4.5@925.53,316.3
PMIC_SDA: R180.2 U4.6 | length 37.7
  Top Layer w6: R180.2@890.94,289.16 898.39,296.61 U4.6@925.53,296.61
PMICOUT_3V3: C44.2 C45.2 C48.1 L11.1 R93.1 R100.2 R198.2 S1.10 S1.11 S1.12 TP10.1 U14.5 U14.6 U14.7 U15.8 | length 1732
  Top Layer w7.87: U15.8@1892.6,275.06 C48.1@1892.6,244.78 C48.1@1892.8,244.98 ; v2(1911.9,451.35) 1933.32,429.93 R100.2@1933.32,359.82
  Top Layer w10: R198.2@770.7,86.51 770.7,119.31 v2(785.27,133.89) ; C44.2@1876.11,-6.42 C45.2@1876.11,19.89 ; TP10.1@1917.5,60.89 L11.1@1917.5,111.24
  Top Layer w12: C48.1@1892.8,244.98 1906.6,244.98 v2(1908.63,247.01)
  L3_SIGNAL 1 w10: v2(785.27,133.89) 801.41,117.76 888.42,117.76 983.59,22.58 983.59,-33.63 999.88,-49.91 1016.31,-49.91 1056.86,-90.46 1348,-90.46 1373.08,-115.54 1373.08,-127.76 1472.64,-227.33 1634.37,-227.33 1710.06,-151.64 1710.06,-125.25 1731.04,-104.27 1792.99,-104.27 1803.66,-93.6 1803.66,14.73 v2(1831.39,42.46)
  Bottom Layer w10: v2(1649.88,92.29) 1654.22,92.29 1669.62,76.89 v2(1671.29,76.89)
  other v2: 1801.12,67.04
PMICVIO_3V3: R176.2 R177.2 R186.1 R187.2 R188.2 R189.2 R190.2 R194.2 | length 274
  Top Layer w8: R188.2@863.91,266.16 863.91,252.53 v4@870.61,245.84
  Top Layer w10: R190.2@870.94,375.35 870.94,391.36 v4(877.82,398.24) ; R176.2@1134.94,284.16 R189.2@1134.94,257.16 1134.94,256.66 1137.28,254.32 v4(1137.28,240.49) ; R176.2@1134.99,284.16 1213.51,284.16 1224.04,273.63 R194.2@1234.41,273.63 R186.1@1265.29,273.63 ; v4(1155.58,413.41) 1155.58,396.25 R187.2@1155.83,396.01 R177.2@1155.83,367.66
  other v4: 871.61,245.84
RADAR_1P0_RF1: C19.2 C23.2 C78.1 C79.1 C100.1 C101.1 L3.2 U1.G5 U1.H5 U1.J5 | length 51.2
  Top Layer w12: U1.J5@1100.39,1357.82 U1.G5@1151.57,1357.82
  other v2: 1104.94,1380.65 1138.19,1381.02
RADAR_1P0_RF2: C20.2 C24.2 C76.1 C77.1 C103.1 C104.1 L2.2 R1.1 U1.C2 U1.D2 | length 111.9
  Top Layer w20: 1228.54,1474.69 1228.54,1434.38 U1.C2@1254.13,1434.38
  Top Layer w22: 1228.54,1474.69 1261.06,1507.2
  other v2: 1273.96,1508.57 1288.58,1530.35
RADAR_1V2: C25.2 C26.2 C27.2 C28.2 C29.2 C30.1 C80.1 C81.1 L7.2 U1.G15 U1.H15 U1.N11 U1.P14 U1.P15 U1.R6 | length 581.5
  Top Layer w10: 960.59,1064.58 972.43,1076.43 U1.P14@972.44,1127.5 ; U1.H15@1125.98,1101.91 1125.97,1049.05 1135.59,1039.43 1135.82,1039.66 v2(1135.82,1040.38) 1138.41,1040.38 1151.56,1053.54 U1.G15@1151.57,1101.91
  Top Layer w12: C28.2@870.28,1361.43 874.13,1361.43 897.27,1338.29 911.08,1338.29 917.08,1332.29 918.08,1332.29 ; 918.35,1332.02 U1.R6@947.05,1332.02
  Top Layer w15: U1.N11@998.03,1204.27 1003.1,1204.28 v2(1015.27,1216.45)
  Top Layer w20: C27.2@842.09,1056.43 862.55,1035.96 873.86,1035.96 895.28,1014.54 C25.2@895.28,1006.43 932.39,1006.43 960.59,1034.63 960.59,1064.58 ; v2(858.93,1385.93) 858.93,1372.78 C28.2@870.28,1361.43 ; C26.2@1134.5,1012.11 1134.5,1038.34 v2@1135.59,1039.43
  Bottom Layer w15: v2(835.49,1089.68) v2(858.21,1085.51)
  other v2: 1135.81,1067.77 1023.19,1195.2
  other v5: 746.74,1528.01 725.73,1646.94 744.24,1678.41 707.84,1713.54 659.39,1751.34
RADAR_1V4_APLL: C22.2 U1.A10 | length 109.3
  Top Layer w12: U1.A10@1305.31,1229.66 1322.36,1229.66
  Top Layer w20: 1322.36,1229.66 1367.36,1229.66 1380.59,1216.43 C22.2@1409.1,1216.43
RADAR_1V4_SYNTH: C18.2 U1.B13 | length 201.1
  Top Layer w4.5: 1290.62,1164.19 1292.6,1166.18 1317.84,1166.18 1322.59,1161.43
  Top Layer w6: U1.B13@1279.52,1153.09 1290.62,1164.19 ; 1322.59,1161.43 1330.7,1153.31
  Top Layer w15: 1330.7,1153.31 1353.7,1130.32 1366.11,1130.32 1375.89,1120.54 1375.89,1108.13 1397.03,1086.99 C18.2@1397.03,1085.14 ; C18.2@1397.03,1085.14 1397.03,1072.84 C18.2@1405.28,1072.84 1405.28,1076.88 C18.2@1397.03,1085.14
RADAR_1V8: C5.2 C9.2 C10.2 C11.2 C12.2 C13.2 C14.2 C15.2 C82.1 C83.1 L1.2 U1.B11 U1.B12 U1.D15 U1.F5 U1.K5 U1.R9 | length 738.7
  Top Layer w10: 1228.34,1089.26 U1.D15@1228.34,1101.91
  Top Layer w12: U1.B12@1279.52,1178.68 1338.33,1178.69 1369.18,1147.84 C5.2@1399.5,1147.84 ; v2@1399.5,1122.52 v2(1400.59,1121.43)
  Top Layer w12.6: 924.94,1258.75 928.23,1255.45 U1.R9@946.84,1255.45
  Top Layer w14: U1.B11@1279.52,1204.27 1283.49,1200.3 1351.72,1200.3 1377.59,1174.43 1457.91,1174.43 C14.2@1485.91,1146.43 1500,1160.52 v5(1500,1175.43)
  Top Layer w15: v2(1057,1378.27) 1074.79,1360.48 U1.K5@1074.8,1357.82 ; U1.F5@1177.16,1357.82 1177.15,1361.78 1183.87,1368.5 1183.87,1370.49 1186.34,1372.96 v2(1186.34,1374.5) ; 1228.34,1089.26 1232.67,1084.93 v6(1232.67,1066.7)
  Top Layer w18: v2@1399.5,1122.52 C5.2@1399.5,1147.84
  Top Layer w20: v2(900.17,1265.5) 918.19,1265.5 924.94,1258.75
  Bottom Layer w20: v2(900.17,1265.5) 901.1,1266.43 C10.2@940.91,1266.43 ; C11.2@991.8,1440.57 991.8,1428.62 1020.43,1400 ; C9.2@1200,1081.11 1218.26,1081.11 v6(1232.67,1066.7)
  Bottom Layer w25: 1020.43,1400 1035.27,1400 v2(1057,1378.27)
  other v5: 1571.06,1109.75 1570.62,1137.76
  other v6: 1021.14,668.83 1069.11,709.64
RADAR_3V3: C16.2 C17.2 C21.2 C88.2 C89.1 R150.2 R153.2 R154.2 R156.2 R169.2 R184.2 R200.2 U1.F15 U1.R10 U10.9 | length 361.6
  Top Layer w10: v2(885.58,1227.49) 887.75,1229.66 U1.R10@947.05,1229.66
  Top Layer w11: C16.2@1163.59,936.11 1163.59,963.71 1166.34,966.46 1173.03,966.46 1193.03,986.46 1193.03,1032.77 1177.15,1048.65 U1.F15@1177.16,1101.91
  Top Layer w20: C17.2@832.09,1276.43 832.09,1233.24 C21.2@826.28,1227.43 885.52,1227.43 v2(885.58,1227.49)
  other v2: 1121.21,922.19 1136.12,939.5 1107.59,940.82 855.18,1223.34 861.29,1248.4
  other v5: 1846.14,1119.32 1871.77,1145.85
RADAR_ANAMUX: R76.1 TP6.1 | length 105.5
  Top Layer w6: R76.1@1490,940.74 R76.1@1490,937.81 1496.58,931.23 1530.98,931.23 1552,952.25 TP6.1@1552,981.43
RADAR_ANATEST2: R73.1 TP3.1 | length 166.8
  Top Layer w8: TP3.1@643.74,1625.33 689.04,1580.04 774.4,1580.04 R73.1@786.69,1567.75
RADAR_ANATEST3: R74.1 TP4.1 | length 60.5
  Top Layer w8: TP4.1@716.44,1506.43 R74.1@776.97,1506.43
RADAR_ANATEST4: R75.1 TP5.1 | length 116.6
  Top Layer w8: TP5.1@578.94,1593.59 621.23,1593.59 631.44,1583.38 654.34,1583.38 R75.1@680.51,1557.21
RADAR_BSS_LOGGER: R60.2 U1.H14 | length 680.8
  Top Layer w4: 1100.16,991 1113.18,1004.02 1113.18,1114.72 U1.H14@1125.98,1127.5
  Top Layer w6: 1100.12,991.05 1086.39,977.33 1086.39,923.51 v2(1118.38,891.52)
  L5_SIGNAL 3 w6: v2(1118.38,891.52) 1144.58,891.52 1161.71,908.65 1161.71,942.98 1193.36,974.63 1216.71,974.63 1309.91,881.43 v2(1384.83,881.43)
  Bottom Layer w6: v2(1384.83,881.43) 1395.9,892.5 R60.2@1435.75,892.5
RADAR_CS1: R156.1 U1.E15 U13.10 | length 1167
  Top Layer w4: v2(1201.59,954.43) 1212.53,965.37 1212.53,1046.85 1202.43,1056.95 1202.43,1101.18 U1.E15@1202.95,1101.7
  Top Layer w6: U13.10@694.28,280.73 v2(727.16,280.73)
  L6_SIGNAL 4 w6: v2(727.16,280.73) 766.94,320.51 766.94,381.93 879.67,494.66 906.78,494.66 917.83,505.7 944.61,505.7 1035.2,596.29 1050.29,596.29 1080.21,626.21 1100.34,626.21 1158.64,684.51 1158.64,703.42 1233.17,777.95 1233.17,922.84 v2(1201.59,954.43)
  Bottom Layer w6: v2(1201.59,954.43) 1227.68,954.43 R156.1@1230,956.74
RADAR_DMM_CLK: J6.15 R15.1 U1.N15 | length 3932.9
  Top Layer w4: 976.59,996.43 976.59,1011.03 998.02,1032.46 U1.N15@998.03,1101.91
  Top Layer w6: 976.59,996.43 976.59,836.33 v2(988.18,824.74) ; v2(1874.86,450.45) 1874.86,501.55 1857.17,519.23 1857.17,586.48 R15.1@1876.87,606.18
  L5_SIGNAL 3 w6: v2(988.18,824.74) 1046.11,824.74 1085.67,785.18 1146.62,785.18 1165.29,766.51 1165.29,676.92 1204.65,637.56 1246.11,637.56 1282.23,601.44 1310.37,601.44 1319.41,592.39 1342.75,592.39 1366.91,568.23 1401.34,568.23 1420.37,587.26 1420.37,614.95 1463.4,657.98 1463.4,790.02 1705.81,1032.43 1705.81,1087.87 v2(1744.12,1126.18)
  L6_SIGNAL 4 w6: v2(1744.12,1126.18) 1744.12,1122.64 1766.89,1099.87 1779.17,1099.87 1883.62,995.42 1934.23,995.42 1946.07,983.59 1946.07,953.11 1978.22,920.96 1978.22,896.04 1999.35,874.91 1999.35,783.79 1916.59,701.03 1916.59,637.91 1887.34,608.67 1887.34,481.19 1874.86,468.71 v2(1874.86,450.45)
  Bottom Layer w6: J6.15@1072.1,34.94 1072.1,78.16 1062.35,87.91 1062.35,145.89 1106.38,189.92 1131.43,189.92 1154.75,213.24 1154.75,221.68 1159.08,226.01 1159.08,251.58 1198.19,290.7 1198.19,314.24 1199.58,315.63 1199.58,373.53 1216.57,390.52 1246.59,390.52 1264.23,372.88 1302.32,372.88 1356.54,427.1 1554.25,427.1 1601.09,380.25 1601.09,336.59 1617.65,320.03 1666.32,320.03 1696.58,350.29 1785.38,350.29 1802.82,332.85 1850.34,332.85 1886.94,369.44 1886.94,408.87 1874.86,420.95 v2(1874.86,450.45)
RADAR_DMM_SYNC: J6.17 R17.1 U1.N14 | length 4127.9
  Top Layer w4: 960.59,993.81 960.59,1009.17 985.47,1034.06 985.47,1114.96 U1.N14@998.03,1127.5
  Top Layer w6: 960.59,993.81 960.59,812.17 v2(970.79,801.97) ; R17.1@1876.87,567.81 1876.87,523.42 v2(1907.54,492.74)
  L5_SIGNAL 3 w6: v2(970.79,801.97) 957.85,814.91 957.85,833.77 969.81,845.73 1045.52,845.73 1091.5,799.75 1149.03,799.75 1217.33,731.44 1217.33,691.97 1250.52,658.77 1250.52,650.12 1287.2,613.44 1315.34,613.44 1323.22,605.56 1349.63,605.56 1374.95,580.23 1396.37,580.23 1408.37,592.23 1408.37,619.92 1441.28,652.83 1441.28,793.71 1692.98,1045.41 1692.98,1117.22 1722.14,1146.38 1757.7,1146.38 1765.32,1138.75 1765.32,1130.01 v2(1775.26,1120.07)
  L6_SIGNAL 4 w6: v2(1775.26,1120.07) 1869.56,1025.77 1979.22,1025.77 2061.86,943.14 2061.86,805.22 1949.86,693.23 1949.86,643.15 1907.54,600.82 v2(1907.54,492.74)
  Bottom Layer w6: J6.17@1091.79,34.94 1091.79,78.33 1073.35,96.77 1073.35,139.92 1111.35,177.92 1134.98,177.92 1165.75,208.68 1165.75,217.13 1171.08,222.46 1171.08,243.51 1209.19,281.62 1209.19,309.69 1210.58,311.07 1210.58,368.98 1221.12,379.52 1242.03,379.52 1260.67,360.88 1307.3,360.88 1361.51,415.1 1549.27,415.1 1589.09,375.28 1589.09,333.03 1613.09,309.03 1684.73,309.03 1714.99,339.29 1762.15,339.29 1808.99,292.45 1850.28,292.45 1932.2,374.36 1932.2,468.09 v2(1907.54,492.74)
RADAR_DP0: J6.19 R18.1 U1.R4 | length 3133.9
  Top Layer w4: 874.43,1435.43 886.59,1435.43 938.61,1383.41 U1.R4@946.84,1383.41
  Top Layer w6: v2(703.89,1465.97) 726.94,1465.97 740.14,1452.78 782.34,1452.78 799.69,1435.43 874.43,1435.43 ; v2(1513.54,744.25) 1598.92,744.25 R18.1@1601.77,747.1
  L3_SIGNAL 1 w6: v2(703.89,1465.97) 676.97,1492.89 619.67,1492.89 548.4,1421.62 531.29,1421.62 485.52,1375.85 485.52,1279.77 525.02,1240.27 557.36,1240.27 623.44,1174.18 630.05,1174.18 668.37,1135.86 716.15,1135.86 757.92,1094.09 757.92,1081.92 887.86,951.97 934.64,951.97 1117.85,768.76 1489.03,768.76 v2(1513.54,744.25)
  L6_SIGNAL 4 w6: v4(1228.58,361.52) 1228.58,428.8 1263.38,463.61 1263.38,581.53 1249.66,595.26 1249.66,659.33 1217.79,691.19 1217.79,708.71 1253.33,744.25 v2(1513.54,744.25)
  Bottom Layer w6: J6.19@1111.47,34.94 1111.47,78.32 1084.35,105.44 1084.35,133.95 1116.32,165.92 1138.54,165.92 1176.75,204.12 1176.75,212.57 1195.56,231.38 1222.61,231.38 1251.43,260.21 1251.43,316.69 1228.58,339.54 v4(1228.58,361.52)
RADAR_DP1: J6.21 R19.1 U1.P5 | length 3318.6
  Top Layer w4: 880.59,1421.43 885.59,1421.43 936.52,1370.5 959.75,1370.5 U1.P5@972.44,1357.82
  Top Layer w6: v2(730.52,1430.27) 750.43,1410.35 814.29,1410.35 825.36,1421.43 880.59,1421.43
  L3_SIGNAL 1 w6: v2(730.52,1430.27) 730.52,1471.45 701.78,1500.18 701.78,1521.43 648.82,1574.39 599.5,1574.39 568.13,1543.02 568.13,1474.01 473.5,1379.38 473.5,1236.54 449.27,1212.31 449.27,1186.95 482.8,1153.42 578.59,1153.42 591.73,1140.28 591.73,1123.54 581.34,1113.15 581.34,1093.43 611.85,1062.92 622.55,1062.92 636.06,1049.41 774.87,1049.41 883.31,940.97 927.67,940.97 1112.67,755.97 1331.46,755.97 v2(1395,692.43)
  L6_SIGNAL 4 w6: v2(1120.9,-43.97) 1144.67,-67.74 1258.7,-67.74 1288.89,-37.55 1288.89,-19.15 1373.83,65.79 1373.83,114.49 1414.33,154.99 1414.33,210.53 1409.57,215.29 1409.57,241.14 1414.33,245.9 1414.33,314.04 1390.99,337.37 1380.91,337.37 1365.67,352.62 1365.67,452.43 1388.94,475.7 1388.94,547.17 1408.2,566.42 1408.2,614.64 1385.24,637.6 1385.24,682.67 v2(1395,692.43)
  Bottom Layer w6: v2(1120.9,-43.97) 1131.16,-33.71 J6.21@1131.16,34.94 ; v2(1395,692.43) 1420.32,717.75 R19.1@1435.75,717.75
RADAR_DP2: J6.23 R20.1 U1.R5 | length 3496.2
  Top Layer w4: 875.59,1406.43 884.86,1406.43 933.68,1357.61 U1.R5@947.05,1357.61
  Top Layer w6: v2(668.58,1414.53) 707.75,1414.53 727.64,1394.64 815.79,1394.64 827.58,1406.43 875.59,1406.43
  L3_SIGNAL 1 w6: v2(668.58,1414.53) 700.98,1414.53 705.45,1410.07 738.89,1410.07 752.66,1423.83 752.66,1445.22 742.86,1455.02 742.86,1476.26 716.5,1502.62 716.5,1522.27 653.38,1585.39 571.97,1585.39 547.55,1560.97 547.55,1514.24 478.3,1444.99 478.3,1407.46 462.5,1391.66 462.5,1246.62 437.27,1221.39 437.27,1181.33 477.18,1141.42 527.56,1141.42 545.07,1123.91 545.07,1094.79 586.32,1053.54 586.32,1034.35 598.15,1022.52 700.05,1022.52 728.85,993.72 802.47,993.72 869.6,926.59 924.08,926.59 1106.71,743.97 1302.46,743.97 v2(1350,696.43)
  L6_SIGNAL 4 w6: v4(1309.72,-27.41) 1385.83,48.7 1385.83,109.52 1425.33,149.02 1425.33,215.09 1420.57,219.85 1420.57,236.58 1425.33,241.34 1425.33,302.24 1440.92,317.83 1440.92,370.8 1393.77,417.95 1393.77,463.56 1399.94,469.73 1399.94,542.61 1428.97,571.64 1428.97,698.95 1411.83,716.09 1369.66,716.09 v2(1350,696.43)
  Bottom Layer w6: J6.23@1150.84,34.94 1150.33,34.42 1150.33,-38.92 1162.16,-50.75 1286.38,-50.75 v4(1309.72,-27.41) ; v2(1350,696.43) 1370.29,716.72 R20.1@1370.29,733.93
RADAR_DP3: J6.25 R21.1 U1.P6 | length 3500.8
  Top Layer w4: v2(768.74,1366.43) 791.74,1343.43 875.16,1343.43 899.09,1319.5 959.7,1319.5 U1.P6@972.44,1332.23
  Top Layer w6: v2(1525.62,774.29) 1588.88,774.29 R21.1@1601.77,787.18
  L3_SIGNAL 1 w6: v2(768.74,1366.43) 739.03,1396.14 688.53,1396.14 682.44,1390.04 653.14,1390.04 632.57,1410.62 537.51,1410.62 497.52,1370.63 497.52,1284.74 529.64,1252.62 560.56,1252.62 628,1185.18 638.37,1185.18 675.7,1147.86 723.4,1147.86 769.92,1101.35 769.92,1085.82 892.77,962.97 940.61,962.97 1118.24,785.33 1495.24,785.33 1506.28,774.29 v2(1525.62,774.29)
  L4_SIGNAL 2 w6: v2(1170.53,-30.55) 1187.57,-30.55 1219.8,1.67 1262.55,1.67 1427.36,166.48 1427.36,197.16 1418.72,205.81 1418.72,257.97 1476.29,315.55 1476.29,475.47 1354.81,596.95 1322.74,596.95 1265.55,654.14 1265.55,669.62 1333.95,738.01 1333.95,867.89 1374.34,908.29 1415.78,908.29 1525.62,798.45 v2(1525.62,774.29)
  Bottom Layer w6: v2(1170.53,-30.55) J6.25@1170.53,34.94
RADAR_DP4: J6.27 R23.1 U1.R7 | length 2940.2
  Top Layer w4: v2(714.09,1376.34) 729.9,1360.53 744.73,1360.53 769.84,1335.43 871.84,1335.43 895.78,1311.5 941.98,1311.5 U1.R7@946.84,1306.64
  L3_SIGNAL 1 w6: v2(714.09,1376.34) 681.63,1376.34 658.85,1353.56 658.85,1298.6 611.33,1251.07 611.33,1219.42 634.57,1196.18 642.93,1196.18 679.25,1159.86 732.65,1159.86 781.92,1110.59 781.92,1090.79 897.3,975.41 945.14,975.41 1121.59,798.95 1532.34,798.95 1545.82,785.48 1545.82,731.76 1505.19,691.14 1433.35,691.14 1414.07,671.86 1397.1,671.86 1388.57,663.32 1388.57,631.24 1364.28,606.95 1322.75,606.95 1308.53,621.17 1308.53,645.24 1313.87,650.58 v2(1313.87,675.43)
  L6_SIGNAL 4 w6: v2(1194.01,106.96) 1194.01,139.92 1202.05,147.96 1165.75,184.26 1165.75,217.13 1179.97,231.35 1179.97,296.02 1216.47,332.52 1240.59,332.52 1273.8,365.72 1273.8,380.56 1305.28,412.05 1305.28,633.33 1313.71,641.75 1313.71,675.27 v2(1313.87,675.43)
  Bottom Layer w6: J6.27@1190.21,34.94 1188.67,36.48 1191.61,39.41 1191.61,104.55 v2(1194.01,106.96) ; v2(1313.87,675.43) 1329.3,690.86 1329.3,722.99 1360.24,753.93 R23.1@1430.75,753.93 R23.1@1435.75,753.93
RADAR_DP5: J6.29 R26.1 U1.P7 | length 2518.8
  Top Layer w4: v2(736.51,1334.8) 755.64,1334.8 763.01,1327.43 868.53,1327.43 893.46,1302.5 933.27,1302.5 941.67,1294.1 959.89,1294.1 U1.P7@972.44,1306.64
  L3_SIGNAL 1 w6: v2(736.51,1334.8) 736.51,1305.7 711.49,1280.67 702.43,1280.67 678.36,1256.6 678.36,1214.93 697.42,1195.86 761.72,1195.86 832.12,1125.47 860.18,1125.47 891.04,1094.61 891.04,1071.84 884.56,1065.36 884.56,1038.29 898.7,1024.14 953.48,1024.14 1131.97,845.66 v2(1368.44,845.66)
  L4_SIGNAL 2 w6: v2(1219.22,-27.7) 1236.61,-10.33 1271.68,-10.33 1469.36,187.35 1469.36,286.64 1488.29,305.57 1488.29,531.6 1384.27,635.62 1384.27,662.79 1374.1,672.96 1374.1,782.38 1368.44,788.03 v2(1368.44,845.66)
  Bottom Layer w6: J6.29@1209.9,34.94 1209.9,-18.38 v2(1219.22,-27.7) ; v2(1368.44,845.66) 1368.44,821.92 1401.79,788.57 R26.1@1430.75,788.57 R26.1@1435.75,788.57
RADAR_DP6: J6.31 R27.1 U1.R8 | length 2576.3
  Top Layer w4: v2(684.06,1341.08) 707.54,1317.6 743.63,1317.6 745.33,1319.29 865.35,1319.29 892.36,1292.29 929.93,1292.29 941.17,1281.05 U1.R8@946.84,1281.05
  L3_SIGNAL 1 w6: v2(684.06,1341.08) 673.26,1330.27 673.26,1294.91 651.73,1273.38 651.73,1206.79 686.66,1171.86 742.1,1171.86 793.92,1120.04 793.92,1095.76 897.94,991.74 947.56,991.74 1128.35,810.95 1394.52,810.95 v2(1405,821.43)
  L6_SIGNAL 4 w6: v2(1223.89,98.52) 1214.14,98.52 1195.11,79.49 1112.66,79.49 1094.03,98.13 1094.03,132.96 1154.75,193.67 1154.75,221.68 1168.97,235.91 1168.97,322.57 1161.12,330.43 1161.12,356.79 1173.58,369.26 1183.18,369.26 1206.72,392.79 1206.72,559.66 1186.89,579.48 1186.89,631.43 1169.64,648.69 1169.64,698.55 1230.95,759.86 1343.43,759.86 v2(1405,821.43)
  Bottom Layer w6: v2(1223.89,98.52) 1229.58,92.83 J6.31@1229.58,34.94 ; v2(1405,821.43) 1433.97,821.43 R27.1@1435.75,823.21
RADAR_DP7: J6.33 R28.1 U1.P8 | length 2877.1
  Top Layer w4: v2(700.53,1299.54) 710.59,1309.6 746.95,1309.6 748.64,1311.29 862.04,1311.29 889.04,1284.29 926.21,1284.29 942.16,1268.34 960.14,1268.34 U1.P8@972.64,1280.84
  L3_SIGNAL 1 w6: v2(700.53,1299.54) 664.09,1263.1 664.09,1212.8 693.04,1183.86 751.91,1183.86 824.77,1111 860.39,1111 878.94,1092.45 878.94,1077.53 871.71,1070.29 871.71,1034.17 897.8,1008.07 951.19,1008.07 1136.31,822.95 1374.3,822.95 1390.36,839.02 1390.36,845.88 v2(1406.71,862.23) 1425.55,862.23 1475.3,812.47 1541.16,812.47 1558.23,795.4 1558.23,573.19 1510.81,525.77 1510.81,187.35 1577.76,120.4 1577.76,20.55 1539.92,-17.29 1539.92,-59.24 1514.65,-84.51 1388.71,-84.51 1355.42,-51.22 1287.17,-51.22 v2(1266.48,-30.53)
  Bottom Layer w6: J6.33@1249.27,34.94 1249.27,-13.31 v2(1266.48,-30.53) ; v2(1406.71,862.23) 1431.38,862.23 R28.1@1435.75,857.86
RADAR_DP8: R124.1 R148.1 | length 1345
  L4_SIGNAL 2 w6: v2(749.92,1015.49) 710.76,1015.49 662.9,967.63 662.9,931.22 668.57,925.55 668.57,777.58 694.92,751.23 694.92,548.14 713.27,529.8 814.09,529.8 866.35,477.54 939.49,477.54 950.68,466.35 950.68,411.68 976.12,386.23 1047.6,386.23 1190.13,243.71 1190.13,226.39 1196.95,219.57 v2(1196.95,204.2)
  Bottom Layer w6: R124.1@671.74,1021.43 677.67,1015.49 v2(749.92,1015.49) ; R148.1@1196.95,175.11 v2(1196.95,204.2)
RADAR_DP9: R125.1 R149.1 | length 1435.8
  L5_SIGNAL 3 w6: v2(780.07,874.71) 780.07,839.91 843.38,776.6 860.12,776.6 871.95,764.77 871.95,748.03 837.07,713.15 837.07,596.33 758.08,517.34 723.37,517.34 708.91,502.88 708.91,451.72 722.69,437.94 722.69,431.96 796.67,357.98 943.88,357.98 955.84,346.03 1088.34,346.03 1179.8,254.56 1179.8,218.17 1174.68,213.05 1174.68,190.54 1183.71,181.5 1211.35,181.5 v2(1228.2,198.34)
  Bottom Layer w6: R125.1@671.74,986.43 683.72,986.43 719.42,950.73 719.42,935.36 v2(780.07,874.71) ; v2(1228.2,198.34) 1228.2,179.97 R149.1@1234.31,173.86
RADAR_DP10: R126.1 R163.1 | length 1466.9
  L3_SIGNAL 1 w6: v2(694.1,944.14) 622.43,872.47 622.43,720.05 656.2,686.28 744.49,686.28 798.88,631.89 798.88,589.93 845.94,542.87 1154.69,542.87 1227.61,469.95 1271.67,469.95 1306.27,435.35 1306.27,375.17 1364.47,316.97 1364.47,275.2 1355.72,266.45 1355.72,246.07 1344.68,235.03 1334.28,235.03 1319.76,220.51 v2(1319.76,194.2)
  Bottom Layer w6: R126.1@656.74,951.43 672.42,951.43 679.71,944.14 v2(694.1,944.14) ; R163.1@1271.67,173.86 1292.01,194.2 v2(1319.76,194.2)
RADAR_DP11: R127.1 R164.1 | length 1424.7
  L3_SIGNAL 1 w6: v2(700.77,915.74) 635.45,850.42 635.45,728.02 660.09,703.39 745.02,703.39 811.41,636.99 811.41,595.9 852.44,554.87 1163.22,554.87 1234.52,483.57 1277.49,483.57 1325.13,435.93 1325.13,373.28 1378.43,319.98 1378.43,273.61 1366.72,261.89 1366.72,238.9 v2(1340.97,213.15)
  Bottom Layer w6: R127.1@656.74,916.43 657.43,915.74 v2(700.77,915.74) ; R164.1@1311.95,167.87 1316.05,171.97 1326.1,171.97 1342.65,188.52 1342.65,211.47 v2(1340.97,213.15) 1340.97,213.42 1343.79,216.24 v2@1342.65,217.39
RADAR_DP12: R128.1 R166.1 | length 1462.3
  L3_SIGNAL 1 w6: v2(702.64,883.98) 702.36,883.98 647.45,829.07 647.45,739.15 670.81,715.79 749.59,715.79 823.41,641.97 823.41,602.42 858.97,566.87 1000.35,566.87 1055.93,622.45 1167.7,622.45 1188.79,601.36 1188.79,556.79 1219.28,526.29 1256.18,526.29 1342.36,440.1 1342.36,373.02 1396.82,318.57 1396.82,281.18 1409.61,268.39 1409.61,225.09 1387.34,202.83 1370.81,202.83 v2(1369.03,201.05)
  Bottom Layer w6: R128.1@656.74,881.43 659.28,883.98 v2(702.64,883.98) ; R166.1@1352.68,167.87 1369.03,184.22 v2(1369.03,201.05)
RADAR_DP13: R129.1 R167.1 | length 1763.3
  L4_SIGNAL 2 w6: v2(701,854.05) 680.57,874.48 680.57,929.1 673.9,935.77 673.9,961.66 706.41,994.16 832.05,994.16 846.64,979.58 1001.39,979.58 1164.11,816.86 1164.11,677.59 1193.3,648.4 1236.32,648.4 1312.09,572.63 1345.19,572.63 1452.29,465.53 1452.29,337.02 1388.88,273.61 1378.43,273.61 1366.72,261.89 1366.72,251.45 1350.3,235.03 1334.28,235.03 1325.14,225.89 1305.48,225.89 1295.47,215.88 1295.47,186.8 1308.27,174 1342.38,174 1351.01,182.63 1358.89,182.63 1360.66,180.85 1392.35,180.85 v2(1394.13,182.63)
  Bottom Layer w6: R129.1@656.74,851.43 659.35,854.05 v2(701,854.05) ; R167.1@1390.77,157.02 1394.13,160.38 v2(1394.13,182.63)
RADAR_DP14: R130.1 R168.1 | length 1385
  L3_SIGNAL 1 w6: v2(693.46,818.46) 686.72,818.46 666.87,798.61 666.87,777.07 682.46,761.48 723.86,761.48 837.3,648.03 837.3,609.16 854.24,592.22 876.2,592.22 929.58,645.6 961.28,645.6 984.33,622.56 1039.26,622.56 1050.15,633.45 1182.17,633.45 1216.94,598.68 1256.38,598.68 1310.83,544.22 1357.04,544.22 1440.77,460.5 v2(1440.77,228.22)
  Bottom Layer w6: R130.1@656.74,816.43 658.77,818.46 v2(693.46,818.46) ; R168.1@1429.92,157.02 1427.36,159.58 1427.36,214.8 v2(1440.77,228.22)
RADAR_DP15: R132.1 R170.1 | length 1266.9
  L3_SIGNAL 1 w6: v2(690.39,788.93) 713.37,788.93 791.76,710.54 915,710.54 989.01,636.53 1033.12,636.53 1042.86,646.27 1186.32,646.27 1212.04,620.55 1251.48,620.55 1315.8,556.22 1362.01,556.22 1460.97,457.27 1460.97,213.23 v2(1447.56,199.82)
  Bottom Layer w6: R132.1@656.74,781.43 664.24,788.93 v2(690.39,788.93) ; v2@1454.61,201.89 1454.61,172.09 1453.69,171.16 R170.1@1467.83,157.02
RADAR_GPIO_0: R3.2 R65.1 R216.2 U1.H13 | length 3153.3
  Top Layer w4: v2(1125.87,1172.29) 1125.97,1172.19 U1.H13@1125.98,1153.09
  Top Layer w6: v2(482.05,136.95) 483.49,136.95 R216.2@516.22,104.22
  L3_SIGNAL 1 w6: v2(189.22,798.8) 189.22,616.35 243.48,562.09 243.48,436.68 311.84,368.32 311.84,285.07 393.12,203.79 v2(472.15,203.79)
  L4_SIGNAL 2 w6: v2(189.22,798.8) 173,815.02 173,931.34 334.48,1092.82 486.53,1092.82 498.52,1080.82 549.01,1080.82 591.73,1123.54 591.73,1144.06 605.98,1158.31 792.78,1158.31 801.99,1149.1 868.38,1149.1 883.91,1164.63 966.69,1164.63 996.71,1134.6 1088.19,1134.6 v2(1125.87,1172.29)
  Bottom Layer w6: R3.2@438.79,203.79 v2(472.15,203.79) 482.05,193.89 v2(482.05,136.95) ; v2(1125.87,1172.29) 1146.26,1151.9 1323.73,1151.9 1433.26,1261.43 1565.72,1261.43 1648.3,1344.01 1903.9,1344.01 1980,1267.92 R65.1@1980,1264.42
